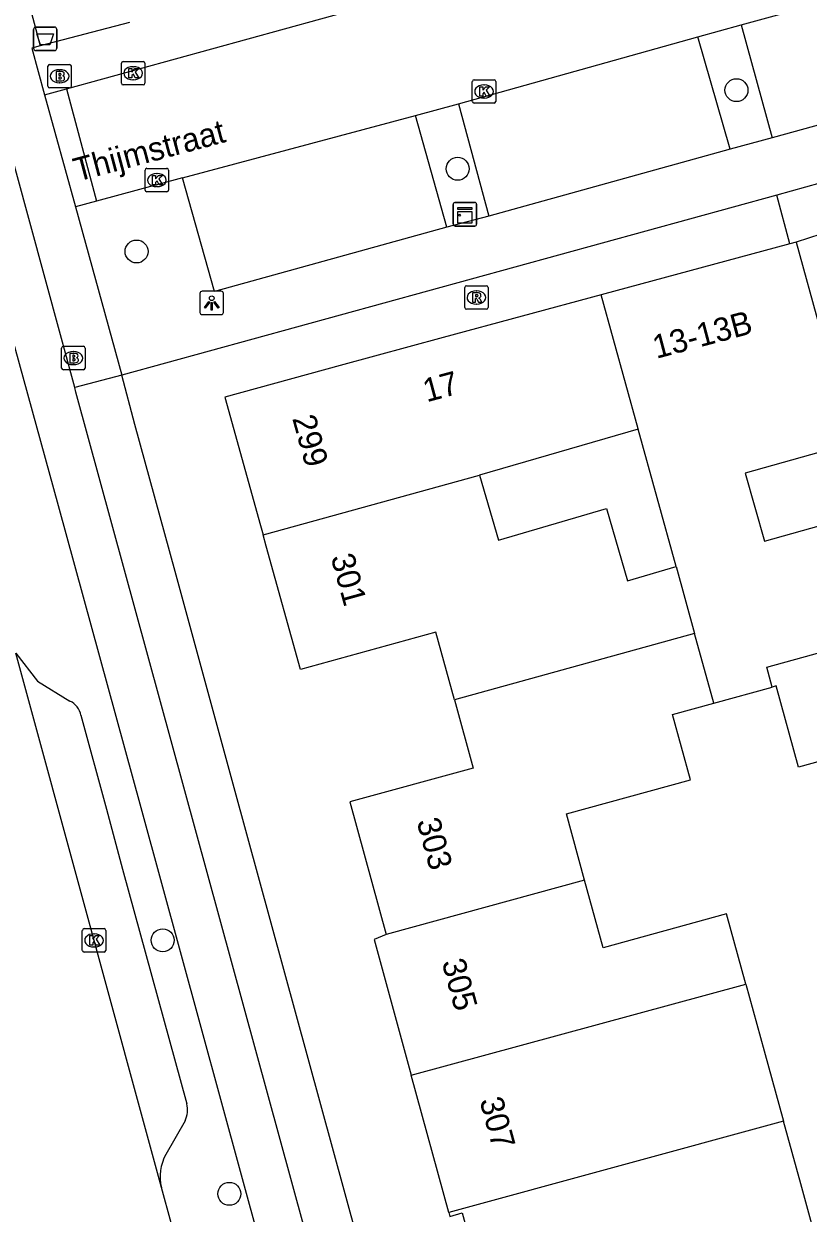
# Model space of a CAD drawing. Extents: x 162542 to 163144, y 380786 to 381511.
# Drawn here: x 162567.3 to 162600.8, y 381111.7 to 381162.4 of the extents above; entities that cross this region are included whole.
import ezdxf

# ---------------------------------------------------------------- set-up
doc = ezdxf.new("R2010")
doc.units = 0
for name, color, linetype in [('IMGEO_Afvalbak', 7, 'Continuous'), ('IMGEO_Boom', 7, 'Continuous'), ('IMGEO_Brandkraan', 7, 'Continuous'), ('IMGEO_Fietspad_gesloten', 7, 'Continuous'), ('IMGEO_Kast', 7, 'Continuous'), ('IMGEO_Kolk', 7, 'Continuous'), ('IMGEO_Lichtpunt', 7, 'Continuous'), ('IMGEO_Openbare_ruimte_label', 7, 'Continuous'), ('IMGEO_Pand', 7, 'Continuous'), ('IMGEO_Pand_nummerreeks', 7, 'Continuous'), ('IMGEO_Parkeervlak_open', 7, 'Continuous'), ('IMGEO_Rijbaan_lokaal_open', 7, 'Continuous'), ('IMGEO_Rijbaan_regionaal_gesloten', 7, 'Continuous'), ('IMGEO_Rioolput', 7, 'Continuous'), ('IMGEO_Voetpad_open', 7, 'Continuous')]:
    doc.layers.add(name, color=color, linetype=linetype)

msp = doc.modelspace()

# ---------------------------------------------------------------- linework, layer by layer
at = {"layer": 'IMGEO_Afvalbak'}
for p, q in [((162567.74, 381161.362), (162567.74, 381162.162)), ((162567.74, 381162.162), (162567.74, 381161.362)), ((162567.84, 381162.262), (162568.63, 381162.262)), ((162568.63, 381162.262), (162567.84, 381162.262)), ((162568.73, 381162.162), (162568.73, 381161.362)), ((162568.73, 381161.362), (162568.73, 381162.162)), ((162568.63, 381161.262), (162567.84, 381161.262)), ((162567.84, 381161.262), (162568.63, 381161.262))]:
    msp.add_line(p, q, dxfattribs=at)
msp.add_lwpolyline([(162567.883, 381161.976), (162568.587, 381161.976), (162568.438, 381161.506), (162568.032, 381161.506), (162567.883, 381161.976)], dxfattribs=at)
for centre, start, end in [((162567.84, 381162.162), 90, 180), ((162567.84, 381162.162), 90, 180), ((162568.63, 381162.162), 0, 90), ((162568.63, 381162.162), 360, 90), ((162567.84, 381161.362), 180, 270), ((162567.84, 381161.362), 180, 270), ((162568.63, 381161.362), 270, 0), ((162568.63, 381161.362), 270, 0)]:
    msp.add_arc(centre, 0.1, start, end, dxfattribs=at)
at = {"layer": 'IMGEO_Boom'}
for centre in [(162597.699, 381159.576), (162585.816, 381156.227), (162572.13, 381152.704), (162573.244, 381123.36), (162576.085, 381112.559)]:
    msp.add_circle(centre, 0.489, dxfattribs=at)
at = {"layer": 'IMGEO_Brandkraan'}
for p, q in [((162568.349, 381159.743), (162568.349, 381160.595)), ((162568.424, 381160.669), (162569.276, 381160.669)), ((162568.837, 381160.449), (162568.862, 381160.449)), ((162569.35, 381160.595), (162569.35, 381159.743)), ((162569.276, 381159.669), (162568.424, 381159.669)), ((162568.86, 381159.889), (162568.835, 381159.889)), ((162568.936, 381147.738), (162568.936, 381148.59)), ((162569.011, 381148.664), (162569.863, 381148.664)), ((162569.424, 381148.444), (162569.449, 381148.444)), ((162569.937, 381148.59), (162569.937, 381147.738)), ((162569.447, 381147.884), (162569.422, 381147.884)), ((162569.863, 381147.664), (162569.011, 381147.664))]:
    msp.add_line(p, q, dxfattribs=at)
for points in [[(162568.349, 381159.743), (162568.349, 381160.595)], [(162568.424, 381160.669), (162569.276, 381160.669)], [(162569.35, 381160.595), (162569.35, 381159.743)], [(162568.697, 381160.369), (162568.697, 381159.969), (162568.91, 381159.969)], [(162568.928, 381160.369), (162568.697, 381160.369)], [(162568.876, 381160.288), (162568.822, 381160.288), (162568.822, 381160.212)], [(162568.822, 381160.212), (162568.875, 381160.212)], [(162568.884, 381160.136), (162568.822, 381160.136), (162568.822, 381160.055)], [(162568.822, 381160.055), (162568.884, 381160.055)], [(162569.276, 381159.669), (162568.424, 381159.669)], [(162568.936, 381147.738), (162568.936, 381148.59)], [(162569.011, 381148.664), (162569.863, 381148.664)], [(162569.284, 381148.364), (162569.284, 381147.964), (162569.497, 381147.964)], [(162569.515, 381148.364), (162569.284, 381148.364)], [(162569.463, 381148.283), (162569.409, 381148.283), (162569.409, 381148.207)], [(162569.937, 381148.59), (162569.937, 381147.738)], [(162569.409, 381148.207), (162569.462, 381148.207)], [(162569.471, 381148.131), (162569.409, 381148.131), (162569.409, 381148.05)], [(162569.409, 381148.05), (162569.471, 381148.05)], [(162569.863, 381147.664), (162569.011, 381147.664)]]:
    msp.add_lwpolyline(points, dxfattribs=at)
for centre, radius, start, end in [((162568.426, 381160.593), 0.0765, 91.552, 178.448), ((162568.426, 381160.593), 0.0765, 91.552, 178.448), ((162569.274, 381160.593), 0.0765, 1.552, 88.448), ((162569.274, 381160.593), 0.0765, 1.552, 88.448), ((162568.877, 381160.25), 0.0379, 267.8285, 90.9355), ((162568.885, 381160.095), 0.0404, 269.8759, 90.5077), ((162568.916, 381160.22), 0.251, 268.6676, 293.5347), ((162568.932, 381160.224), 0.145, 59.4692, 91.5367), ((162568.957, 381160.271), 0.0922, 285.5137, 58.1501), ((162568.962, 381160.079), 0.105, 301.3115, 78.989), ((162568.426, 381159.745), 0.0765, 181.552, 268.448), ((162568.426, 381159.745), 0.0765, 181.552, 268.448), ((162569.274, 381159.745), 0.0765, 271.552, 358.448), ((162569.274, 381159.745), 0.0765, 271.552, 358.448), ((162569.013, 381148.588), 0.0765, 91.552, 178.448), ((162569.013, 381148.588), 0.0765, 91.552, 178.448), ((162569.464, 381148.245), 0.0379, 267.8285, 90.9355), ((162569.519, 381148.219), 0.145, 59.4692, 91.5367), ((162569.544, 381148.266), 0.0922, 285.5137, 58.1501), ((162569.861, 381148.588), 0.0765, 1.552, 88.448), ((162569.861, 381148.588), 0.0765, 1.552, 88.448), ((162569.472, 381148.09), 0.0404, 269.8759, 90.5077), ((162569.503, 381148.215), 0.251, 268.6676, 293.5347), ((162569.549, 381148.074), 0.105, 301.3115, 78.989), ((162569.013, 381147.74), 0.0765, 181.552, 268.448), ((162569.013, 381147.74), 0.0765, 181.552, 268.448), ((162569.861, 381147.74), 0.0765, 271.552, 358.448), ((162569.861, 381147.74), 0.0765, 271.552, 358.448)]:
    msp.add_arc(centre, radius, start, end, dxfattribs=at)
for centre, major_axis, ratio, start_param, end_param in [((162568.836, 381160.169), (-0.387, 0.002), 0.722429, 4.712389, 7.853982), ((162568.861, 381160.169), (-0.39, 0.002), 0.717154, 1.570796, 4.712389), ((162569.423, 381148.164), (-0.387, 0.002), 0.722429, 4.712389, 7.853982), ((162569.448, 381148.164), (-0.39, 0.002), 0.717154, 1.570796, 4.712389)]:
    msp.add_ellipse(centre, major_axis=major_axis, ratio=ratio, start_param=start_param, end_param=end_param, dxfattribs=at)
at = {"layer": 'IMGEO_Fietspad_gesloten'}
for points in [[(162569.494, 381146.907), (162565.078, 381163.085), (162555.861, 381196.62), (162551.297, 381213.188)], [(162551.566, 381204.656), (162553.917, 381196.083), (162563.738, 381160.379), (162566.376, 381150.67), (162568.784, 381141.877), (162572.307, 381129.01), (162578.269, 381107.238), (162579.233, 381103.719), (162587.35, 381073.966)], [(162627.119, 380935.366), (162613.988, 380983.443), (162609.049, 381001.918), (162603.581, 381022.358), (162590.197, 381071.276), (162588.809, 381076.324), (162582.093, 381100.864), (162580.289, 381107.447), (162569.546, 381146.716), (162569.494, 381146.907)]]:
    msp.add_lwpolyline(points, dxfattribs=at)
at = {"layer": 'IMGEO_Kast'}
for p, q in [((162585.624, 381153.863), (162585.624, 381154.704)), ((162585.624, 381154.704), (162585.624, 381153.863)), ((162585.699, 381154.788), (162586.54, 381154.788)), ((162586.54, 381154.788), (162585.699, 381154.788)), ((162586.624, 381154.713), (162586.624, 381153.872)), ((162586.624, 381153.872), (162586.624, 381154.713)), ((162586.549, 381153.788), (162585.708, 381153.788)), ((162585.708, 381153.788), (162586.549, 381153.788))]:
    msp.add_line(p, q, dxfattribs=at)
for points in [[(162585.819, 381154.578), (162586.419, 381154.578), (162586.419, 381154.493), (162585.819, 381154.493), (162585.819, 381154.578)], [(162585.819, 381154.403), (162586.419, 381154.403), (162586.419, 381153.914), (162585.819, 381153.914), (162585.819, 381154.403)]]:
    msp.add_lwpolyline(points, dxfattribs=at)
msp.add_circle((162585.903, 381154.252), 0.0377, dxfattribs=at)
for centre, start, end in [((162585.702, 381154.71), 92.4484, 184.2845), ((162585.702, 381154.71), 92.4484, 184.2845), ((162586.546, 381154.71), 2.4484, 94.2845), ((162586.546, 381154.71), 2.4484, 94.2845), ((162585.702, 381153.866), 182.4484, 274.2845), ((162585.702, 381153.866), 182.4484, 274.2845), ((162586.546, 381153.866), 272.4484, 4.2845), ((162586.546, 381153.866), 272.4484, 4.2845)]:
    msp.add_arc(centre, 0.0779, start, end, dxfattribs=at)
at = {"layer": 'IMGEO_Kolk'}
for p, q in [((162571.485, 381159.871), (162571.485, 381160.723)), ((162571.56, 381160.797), (162572.412, 381160.797)), ((162571.973, 381160.577), (162571.998, 381160.577)), ((162572.486, 381160.723), (162572.486, 381159.871)), ((162571.996, 381160.017), (162571.971, 381160.017)), ((162586.441, 381159.096), (162586.441, 381159.948)), ((162586.516, 381160.022), (162587.368, 381160.022)), ((162587.442, 381159.948), (162587.442, 381159.096)), ((162572.412, 381159.797), (162571.56, 381159.797)), ((162586.929, 381159.802), (162586.954, 381159.802)), ((162587.368, 381159.022), (162586.516, 381159.022)), ((162586.952, 381159.242), (162586.927, 381159.242)), ((162572.494, 381155.32), (162572.494, 381156.172)), ((162572.569, 381156.246), (162573.421, 381156.246)), ((162572.982, 381156.026), (162573.007, 381156.026)), ((162573.495, 381156.172), (162573.495, 381155.32)), ((162573.005, 381155.466), (162572.98, 381155.466)), ((162573.421, 381155.246), (162572.569, 381155.246)), ((162569.819, 381122.931), (162569.819, 381123.783)), ((162569.894, 381123.857), (162570.746, 381123.857)), ((162570.307, 381123.637), (162570.332, 381123.637)), ((162570.82, 381123.783), (162570.82, 381122.931)), ((162570.33, 381123.077), (162570.305, 381123.077)), ((162570.746, 381122.857), (162569.894, 381122.857))]:
    msp.add_line(p, q, dxfattribs=at)
for points in [[(162571.485, 381159.871), (162571.485, 381160.723)], [(162571.56, 381160.797), (162572.412, 381160.797)], [(162571.806, 381160.497), (162571.929, 381160.497), (162571.929, 381160.346), (162572.059, 381160.497), (162572.223, 381160.497), (162572.077, 381160.346), (162572.23, 381160.097), (162572.078, 381160.097), (162571.993, 381160.261), (162571.929, 381160.194), (162571.929, 381160.097), (162571.806, 381160.097), (162571.806, 381160.497)], [(162572.486, 381160.723), (162572.486, 381159.871)], [(162586.441, 381159.096), (162586.441, 381159.948)], [(162586.516, 381160.022), (162587.368, 381160.022)], [(162587.442, 381159.948), (162587.442, 381159.096)], [(162572.412, 381159.797), (162571.56, 381159.797)], [(162586.762, 381159.722), (162586.885, 381159.722), (162586.885, 381159.571), (162587.015, 381159.722), (162587.179, 381159.722), (162587.033, 381159.571), (162587.186, 381159.322), (162587.034, 381159.322), (162586.949, 381159.486), (162586.885, 381159.419), (162586.885, 381159.322), (162586.762, 381159.322), (162586.762, 381159.722)], [(162587.368, 381159.022), (162586.516, 381159.022)], [(162572.494, 381155.32), (162572.494, 381156.172)], [(162572.569, 381156.246), (162573.421, 381156.246)], [(162572.815, 381155.946), (162572.938, 381155.946), (162572.938, 381155.795), (162573.068, 381155.946), (162573.232, 381155.946), (162573.086, 381155.795), (162573.239, 381155.546), (162573.087, 381155.546), (162573.002, 381155.71), (162572.938, 381155.643), (162572.938, 381155.546), (162572.815, 381155.546), (162572.815, 381155.946)], [(162573.495, 381156.172), (162573.495, 381155.32)], [(162573.421, 381155.246), (162572.569, 381155.246)], [(162569.819, 381122.931), (162569.819, 381123.783)], [(162569.894, 381123.857), (162570.746, 381123.857)], [(162570.14, 381123.557), (162570.263, 381123.557), (162570.263, 381123.406), (162570.393, 381123.557), (162570.557, 381123.557), (162570.411, 381123.406), (162570.564, 381123.157), (162570.412, 381123.157), (162570.327, 381123.321), (162570.263, 381123.254), (162570.263, 381123.157), (162570.14, 381123.157), (162570.14, 381123.557)], [(162570.82, 381123.783), (162570.82, 381122.931)], [(162570.746, 381122.857), (162569.894, 381122.857)]]:
    msp.add_lwpolyline(points, dxfattribs=at)
for centre, start, end in [((162571.562, 381160.721), 91.552, 178.448), ((162571.562, 381160.721), 91.552, 178.448), ((162572.41, 381160.721), 1.552, 88.448), ((162572.41, 381160.721), 1.552, 88.448), ((162586.518, 381159.946), 91.552, 178.448), ((162586.518, 381159.946), 91.552, 178.448), ((162587.366, 381159.946), 1.552, 88.448), ((162587.366, 381159.946), 1.552, 88.448), ((162571.562, 381159.873), 181.552, 268.448), ((162571.562, 381159.873), 181.552, 268.448), ((162572.41, 381159.873), 271.552, 358.448), ((162572.41, 381159.873), 271.552, 358.448), ((162586.518, 381159.098), 181.552, 268.448), ((162586.518, 381159.098), 181.552, 268.448), ((162587.366, 381159.098), 271.552, 358.448), ((162587.366, 381159.098), 271.552, 358.448), ((162572.571, 381156.17), 91.552, 178.448), ((162572.571, 381156.17), 91.552, 178.448), ((162573.419, 381156.17), 1.552, 88.448), ((162573.419, 381156.17), 1.552, 88.448), ((162572.571, 381155.322), 181.552, 268.448), ((162572.571, 381155.322), 181.552, 268.448), ((162573.419, 381155.322), 271.552, 358.448), ((162573.419, 381155.322), 271.552, 358.448), ((162569.896, 381123.781), 91.552, 178.448), ((162569.896, 381123.781), 91.552, 178.448), ((162570.744, 381123.781), 1.552, 88.448), ((162570.744, 381123.781), 1.552, 88.448), ((162569.896, 381122.933), 181.552, 268.448), ((162569.896, 381122.933), 181.552, 268.448), ((162570.744, 381122.933), 271.552, 358.448), ((162570.744, 381122.933), 271.552, 358.448)]:
    msp.add_arc(centre, 0.0765, start, end, dxfattribs=at)
for centre, major_axis, ratio, start_param, end_param in [((162571.972, 381160.297), (-0.387, 0.002), 0.722429, 4.712389, 7.853982), ((162571.997, 381160.297), (-0.39, 0.002), 0.717154, 1.570796, 4.712389), ((162586.928, 381159.522), (-0.387, 0.002), 0.722429, 4.712389, 7.853982), ((162586.953, 381159.522), (-0.39, 0.002), 0.717154, 1.570796, 4.712389), ((162572.981, 381155.746), (-0.387, 0.002), 0.722429, 4.712389, 7.853982), ((162573.006, 381155.746), (-0.39, 0.002), 0.717154, 1.570796, 4.712389), ((162570.306, 381123.357), (-0.387, 0.002), 0.722429, 4.712389, 7.853982), ((162570.331, 381123.357), (-0.39, 0.002), 0.717154, 1.570796, 4.712389)]:
    msp.add_ellipse(centre, major_axis=major_axis, ratio=ratio, start_param=start_param, end_param=end_param, dxfattribs=at)
at = {"layer": 'IMGEO_Lichtpunt'}
for p, q in [((162574.834, 381150.915), (162574.834, 381150.108)), ((162574.834, 381150.915), (162574.834, 381150.108)), ((162575.736, 381151.01), (162574.928, 381151.01)), ((162575.736, 381151.01), (162574.928, 381151.01)), ((162575.83, 381150.108), (162575.83, 381150.915)), ((162575.83, 381150.108), (162575.83, 381150.915)), ((162574.928, 381150.014), (162575.736, 381150.014)), ((162574.928, 381150.014), (162575.736, 381150.014))]:
    msp.add_line(p, q, dxfattribs=at)
for points in [[(162575.208, 381150.579), (162575.247, 381150.551), (162575.059, 381150.289), (162575.021, 381150.316), (162575.208, 381150.579)], [(162575.31, 381150.531), (162575.357, 381150.531), (162575.357, 381150.209), (162575.31, 381150.209), (162575.31, 381150.531)], [(162575.42, 381150.551), (162575.458, 381150.578), (162575.645, 381150.316), (162575.606, 381150.288), (162575.42, 381150.551)]]:
    msp.add_lwpolyline(points, dxfattribs=at)
msp.add_circle((162575.333, 381150.713), 0.0994, dxfattribs=at)
for centre, start, end in [((162574.928, 381150.915), 90, 180), ((162574.928, 381150.915), 90, 180), ((162575.736, 381150.915), 0, 90), ((162575.736, 381150.915), 0, 90), ((162574.928, 381150.108), 180, 270), ((162574.928, 381150.108), 180, 270), ((162575.736, 381150.108), 270, 0), ((162575.736, 381150.108), 270, 360)]:
    msp.add_arc(centre, 0.0946, start, end, dxfattribs=at)
at = {"layer": 'IMGEO_Pand'}
for points in [[(162599.971, 381153.035), (162591.933, 381150.858)], [(162600.237, 381153.107), (162602.258, 381145.771), (162602.133, 381145.736), (162602.48, 381144.497), (162598.075, 381143.264), (162598.887, 381140.365), (162603.291, 381141.599), (162604.699, 381136.572)], [(162600.237, 381153.107), (162599.971, 381153.035)], [(162591.933, 381150.858), (162585.197, 381149.033), (162580.802, 381147.843), (162575.898, 381146.497), (162577.41, 381141.036), (162577.522, 381140.631)], [(162593.509, 381145.14), (162593.508, 381145.143), (162591.933, 381150.858)], [(162593.509, 381145.14), (162586.745, 381143.172)], [(162595.123, 381139.282), (162593.509, 381145.14)], [(162577.522, 381140.631), (162586.745, 381143.172)], [(162586.745, 381143.172), (162587.553, 381140.411), (162592.161, 381141.758), (162593.061, 381138.679), (162595.123, 381139.282)], [(162585.676, 381133.608), (162584.883, 381136.49), (162579.111, 381134.892), (162577.653, 381140.157), (162577.522, 381140.631)], [(162595.123, 381139.282), (162595.911, 381136.423)], [(162595.911, 381136.423), (162585.676, 381133.608)], [(162596.728, 381133.462), (162595.911, 381136.423)], [(162599.227, 381134.15), (162598.993, 381134.999), (162604.699, 381136.572)], [(162596.728, 381133.462), (162599.227, 381134.15)], [(162605.484, 381133.2), (162605.755, 381132.226), (162600.343, 381130.735), (162599.39, 381134.195), (162599.227, 381134.15)], [(162585.676, 381133.608), (162586.477, 381130.696), (162581.222, 381129.26), (162582.766, 381123.612)], [(162591.228, 381125.915), (162590.45, 381128.74), (162595.745, 381130.199), (162594.979, 381132.981), (162596.728, 381133.462)], [(162591.228, 381125.915), (162582.766, 381123.612)], [(162598.095, 381121.495), (162597.272, 381124.484), (162592.02, 381123.037), (162591.228, 381125.915)], [(162582.766, 381123.612), (162582.258, 381123.387), (162583.836, 381117.613)], [(162583.836, 381117.613), (162598.095, 381121.495)], [(162598.095, 381121.495), (162598.877, 381118.656), (162599.706, 381115.648)], [(162585.434, 381111.762), (162583.836, 381117.613)], [(162599.706, 381115.648), (162585.434, 381111.762)], [(162604.769, 381110.039), (162604.657, 381110.447), (162604.526, 381110.924), (162601.255, 381110.023), (162600.441, 381112.98), (162599.706, 381115.648)], [(162585.434, 381111.762), (162585.479, 381111.599), (162586.009, 381111.743), (162587.563, 381106.055), (162593.969, 381107.805), (162599.216, 381109.238), (162599.98, 381106.441)]]:
    msp.add_lwpolyline(points, dxfattribs=at)
at = {"layer": 'IMGEO_Parkeervlak_open'}
for points in [[(162597.893, 381162.354), (162599.225, 381157.549)], [(162597.43, 381157.064), (162596.058, 381161.854)], [(162585.856, 381158.999), (162587.148, 381154.203)], [(162585.357, 381153.744), (162584.013, 381158.504)], [(162566.984, 381135.586), (162567.913, 381134.398), (162569.293, 381133.553)], [(162569.759, 381132.945), (162570.843, 381128.945), (162571.537, 381126.385), (162574.277, 381116.399)], [(162574.196, 381115.665), (162573.38, 381114.236)]]:
    msp.add_lwpolyline(points, dxfattribs=at)
for centre, radius, start, end in [((162568.919, 381132.784), 0.855, 10.8509, 64.0856), ((162573.173, 381116.149), 1.132, 334.6697, 12.7356), ((162575.098, 381113.288), 1.962, 151.1123, 193.7409)]:
    msp.add_arc(centre, radius, start, end, dxfattribs=at)
at = {"layer": 'IMGEO_Rijbaan_lokaal_open'}
for points in [[(162569.139, 381159.638), (162600.111, 381168.166), (162605.985, 381169.742), (162619.18, 381173.408)], [(162597.893, 381162.354), (162610.208, 381165.73)], [(162596.058, 381161.854), (162597.893, 381162.354)], [(162585.856, 381158.999), (162596.058, 381161.854)], [(162569.139, 381159.638), (162570.418, 381154.845)], [(162584.013, 381158.504), (162585.856, 381158.999)], [(162574.094, 381155.842), (162584.013, 381158.504)], [(162574.094, 381155.842), (162570.418, 381154.845)]]:
    msp.add_lwpolyline(points, dxfattribs=at)
at = {"layer": 'IMGEO_Rijbaan_regionaal_gesloten'}
for points in [[(162573.192, 381112.822), (162566.984, 381135.586)], [(162574.847, 381106.808), (162573.192, 381112.822)]]:
    msp.add_lwpolyline(points, dxfattribs=at)
at = {"layer": 'IMGEO_Rioolput'}
for p, q in [((162586.115, 381150.318), (162586.115, 381151.17)), ((162586.19, 381151.244), (162587.042, 381151.244)), ((162586.603, 381151.024), (162586.628, 381151.024)), ((162587.116, 381151.17), (162587.116, 381150.318)), ((162586.626, 381150.464), (162586.601, 381150.464)), ((162587.042, 381150.244), (162586.19, 381150.244))]:
    msp.add_line(p, q, dxfattribs=at)
for points in [[(162586.115, 381150.318), (162586.115, 381151.17)], [(162586.19, 381151.244), (162587.042, 381151.244)], [(162586.704, 381150.942), (162586.452, 381150.944), (162586.452, 381150.544)], [(162586.63, 381150.863), (162586.576, 381150.863), (162586.576, 381150.782)], [(162587.116, 381151.17), (162587.116, 381150.318)], [(162586.452, 381150.544), (162586.576, 381150.544), (162586.576, 381150.706), (162586.587, 381150.706)], [(162586.576, 381150.782), (162586.628, 381150.782)], [(162586.634, 381150.677), (162586.705, 381150.544), (162586.845, 381150.544), (162586.78, 381150.67)], [(162587.042, 381150.244), (162586.19, 381150.244)]]:
    msp.add_lwpolyline(points, dxfattribs=at)
for centre, radius, start, end in [((162586.192, 381151.168), 0.0765, 91.552, 178.448), ((162586.192, 381151.168), 0.0765, 91.552, 178.448), ((162586.636, 381150.767), 0.0964, 77.0061, 93.1865), ((162586.65, 381150.824), 0.0378, 276.6634, 79.6772), ((162586.703, 381150.832), 0.109, 350.3612, 89.416), ((162586.701, 381150.832), 0.112, 277.5842, 350.9817), ((162587.04, 381151.168), 0.0765, 1.552, 88.448), ((162587.04, 381151.168), 0.0765, 1.552, 88.448), ((162586.192, 381150.32), 0.0765, 181.552, 268.448), ((162586.192, 381150.32), 0.0765, 181.552, 268.448), ((162586.586, 381150.653), 0.0533, 26.0293, 88.6989), ((162586.612, 381150.971), 0.19, 274.7715, 282.9687), ((162586.685, 381150.617), 0.108, 29.5134, 73.7905), ((162587.04, 381150.32), 0.0765, 271.552, 358.448), ((162587.04, 381150.32), 0.0765, 271.552, 358.448)]:
    msp.add_arc(centre, radius, start, end, dxfattribs=at)
for centre, major_axis, ratio, start_param, end_param in [((162586.602, 381150.744), (-0.387, 0.002), 0.722429, 4.712389, 7.853982), ((162586.627, 381150.744), (-0.39, 0.002), 0.717154, 1.570796, 4.712389)]:
    msp.add_ellipse(centre, major_axis=major_axis, ratio=ratio, start_param=start_param, end_param=end_param, dxfattribs=at)
at = {"layer": 'IMGEO_Voetpad_open'}
for points in [[(162563.482, 381189.641), (162563.656, 381177.51), (162564.284, 381175.444), (162567.392, 381163.83), (162568.023, 381161.469)], [(162571.831, 381162.454), (162568.023, 381161.469)], [(162568.023, 381161.469), (162567.663, 381161.371), (162568.211, 381159.383)], [(162611.546, 381160.95), (162602.261, 381158.387), (162599.225, 381157.549)], [(162568.211, 381159.383), (162569.139, 381159.638)], [(162568.211, 381159.383), (162569.53, 381154.605)], [(162599.225, 381157.549), (162597.43, 381157.064)], [(162597.43, 381157.064), (162587.148, 381154.203)], [(162585.357, 381153.744), (162575.45, 381151.004), (162574.094, 381155.842)], [(162601.824, 381153.619), (162601.256, 381155.615), (162599.413, 381155.1)], [(162599.413, 381155.1), (162571.507, 381147.44)], [(162599.971, 381153.035), (162599.413, 381155.1)], [(162570.418, 381154.845), (162569.53, 381154.605)], [(162569.53, 381154.605), (162571.507, 381147.44)], [(162587.148, 381154.203), (162585.357, 381153.744)], [(162601.824, 381153.619), (162600.237, 381153.107)], [(162571.507, 381147.44), (162569.494, 381146.907)], [(162586.182, 381093.351), (162583.138, 381104.821), (162576.291, 381129.86), (162573.771, 381139.072), (162572.06, 381145.331), (162571.507, 381147.44)]]:
    msp.add_lwpolyline(points, dxfattribs=at)

# ---------------------------------------------------------------- texts
at = {"layer": 'IMGEO_Openbare_ruimte_label'}
msp.add_text('Thijmstraat', height=1, rotation=14.9536, dxfattribs=at).set_placement((162569.6, 381155.674))
at = {"layer": 'IMGEO_Pand_nummerreeks'}
for s, rotation, p in [('13-13B', 14.9026, (162594.284, 381148.128)), ('17', 15.1375, (162584.496, 381146.275)), ('299', 285.4754, (162578.761, 381145.597)), ('301', 285.4754, (162580.399, 381139.685)), ('303', 285.2894, (162584.061, 381128.43)), ('305', 285.2827, (162585.131, 381122.433)), ('307', 285.2806, (162586.741, 381116.539))]:
    msp.add_text(s, height=1, rotation=rotation, dxfattribs=at).set_placement(p)

doc.saveas('drawing.dxf')
